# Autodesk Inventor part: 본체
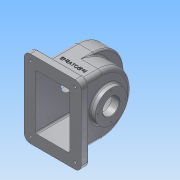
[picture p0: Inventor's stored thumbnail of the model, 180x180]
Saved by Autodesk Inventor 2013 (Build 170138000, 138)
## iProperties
Created: 2017-11
Part Number: 본체
Material: 알루미늄 6061
Document SubType Name: Modeling
Designer: Administrator
Density: 2.71 g/cm^3
Mass: 1079.31 g
Surface Area: 1186.21 cm^2
Volume: 398.271 cm^3
Author: Administrator
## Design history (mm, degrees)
sketch "스케치1"
  geometry: L1 (80, -58)-(15, -58); L2 (80, 58)-(15, 58); L3 (15, 58)-(15, -58); A1 r 58 centre (80, 0) between (80, -58) and (80, 58); 3 further points
  constraints: 6 end point, 2 horizontal alignment, 2 point on circle, 2 tangent, 1 centre point, 1 coincident, 1 horizontal, 1 parallel, 1 perpendicular
  dimensions: "d0" = 116 diameter of A1; "d7" = 15 distance from line of L3 point (0, 0); "d8" = 80 distance of point (0, 0) A1.centre
extrude "돌출1" new body sketch "스케치1" distance "d5" = 38; taper "d6" = 0 deg
sketch "스케치2"
  geometry: L1 (-58, 80)-(-58, 15) reference; L2 (-58, 15)-(58, 15) reference; L3 (58, 15)-(58, 80) reference; A1 r 58 centre (0, 80) between (58, 80) and (-58, 80) reference; A2 r 58 centre (0, 57) between (58, 57) and (-58, 57); 1 further point
  constraints: 2 point on circle, 2 point on line, 1 centre point, 1 vertical alignment
  dimensions: "d9" = 116 diameter of A2; "d11" = 57 distance of point (0, 0) A2.centre
extrude "돌출2" join sketch "스케치2" distance "d12" = 38; taper "d13" = 0 deg
sketch "스케치3"
  geometry: L1 (-93, 75)-(17, 75); L2 (17, 75)-(17, -75); L3 (17, -75)-(-93, -75); L4 (-93, -75)-(-93, 75); L5 (-93, 75)-(17, -75); L6 (17, 75)-(-93, -75); L7 (0, 58)-(0, -58) reference; L8 (0, -58)-(-76, -58) reference; L9 (-76, 58)-(-76, -58) reference; L10 (0, 58)-(-76, 58) reference; L11 (0, -58)-(0, 58) reference; L12 (0, 58)-(-38, 58) reference; L13 (-38, -58)-(-38, 58) reference; L14 (0, -58)-(-38, -58) reference; 2 further points
  constraints: 12 end point, 2 midpoint, 2 parallel, 1 horizontal, 1 perpendicular
  dimensions: "d14" = 110 distance of L2.end L3.end; "d16" = 150 distance of L1.end L2.end; "d17" = 55 horizontal distance of L13.start L2.end; "d18" = 75 distance from line of point (0, 0) L3
extrude "돌출3" join sketch "스케치3" distance "d19" = 15; taper "d20" = 0 deg
feature "쉘1" dims "d21" = 20, "d22" = 5
fillet "모깎기1" dims "d23" = 12, "d24" = 3, "d25" = 8
sketch "스케치4"
  geometry: L1 (63, 0)-(-63, 0) reference; C1 r 37.5 at (0, 65); A1 r 50 centre (0, 80) between (50, 80) and (-50, 80) reference; 1 further point
  constraints: 1 centre point, 1 vertical alignment
  dimensions: "d26" = 75 diameter of C1; "d27" = 65 distance from line of L1 C1.centre
extrude "돌출4" join sketch "스케치4" distance "d28" = 9; taper "d29" = 0 deg
sketch "스케치5"
  geometry: L1 (63, 0)-(-63, 0) reference; C1 r 31 at (0, 65); A1 r 50 centre (0, 57) between (50, 57) and (-50, 57) reference; 1 further point
  constraints: 1 centre point, 1 vertical alignment
  dimensions: "d30" = 62 diameter of C1; "d31" = 65 distance from line of L1 C1.centre
extrude "돌출5" join sketch "스케치5" distance "d32" = 10; taper "d33" = 0 deg
hole "구멍1" diameter "d37" = 32; stored, may be unused: countersink angle "d41" = 90 deg, drill point angle "d43" = 118 deg; dims "d35" = 10, "d36" = 10, "d38" = 6, "d39" = 4, "d40" = 2, "d42" = 8
sketch "스케치6" dims "d44" = 58
  geometry: L1 (0, 0)-(0, 29); C1 r 37.5 at (0, 0) reference; 1 further point
  constraints: 2 end point, 1 coincident, 1 vertical, 1 vertical alignment, 2 other
hole "구멍2" sketch "스케치6" at (0, 29) diameter "d45" = 2.459; stored, may be unused: countersink angle "d49" = 90 deg, drill point angle "d51" = 118 deg; dims "d46" = 6, "d47" = 4, "d48" = 2, "d50" = 8
sketch "스케치7" dims "d55" = 52
  geometry: L1 (0, 0)-(0, 26); C1 r 31 at (0, 0) reference; 1 further point
  constraints: 2 end point, 1 coincident, 1 vertical, 1 vertical alignment, 2 other
hole "구멍3" sketch "스케치7" at (0, 26) diameter "d56" = 2.459; stored, may be unused: countersink angle "d60" = 90 deg, drill point angle "d62" = 118 deg; dims "d57" = 6, "d58" = 4, "d59" = 2, "d61" = 8
node "작업 평면1"
sketch "스케치8"
  geometry: C1 r 6 at (-19, 0); 1 further point
  constraints: 1 centre point, 1 horizontal alignment
  dimensions: "d67" = 19 distance of C1.centre point (0, 0); "d68" = 12 diameter of C1
extrude "돌출6" join sketch "스케치8" stored distance "d69" = 10; taper "d70" = 0 deg
fillet "모깎기2" dims "d34" = 3
hole "구멍4" diameter "d73" = 4.459; stored, may be unused: countersink angle "d77" = 90 deg, drill point angle "d79" = 118 deg; dims "d71" = 10, "d72" = 10, "d74" = 6, "d75" = 4, "d76" = 2, "d78" = 8
sketch "스케치9"
  geometry: A1 r 9 centre (81, -63) between (81, -72) and (90, -63) reference; A2 r 9 centre (81, 63) between (90, 63) and (81, 72) reference; A3 r 9 centre (-5, 63) between (-5, 72) and (-14, 63) reference; A4 r 9 centre (-5, -63) between (-14, -63) and (-5, -72) reference; 1 further point
hole "구멍5" sketch "스케치9" at (-5, -63), (81, -63), (-5, 63), (81, 63) diameter "d80" = 5; stored, may be unused: countersink angle "d84" = 90 deg, drill point angle "d86" = 0 deg; dims "d81" = 6, "d82" = 12, "d83" = 5, "d85" = 8
sketch "스케치10"
  geometry: L1 (-35, 23)-(-35, -39) reference; L2 (-40, -57)-(-52, -57) reference; 2 further points
  constraints: 1 other
  dimensions: "d87" = 38 distance from line of point (3, -17) L1; "d88" = 40 distance from line of point (3, -17) L2
feature "엠보싱1" sketch "스케치10" dims "d0" = 116, "d7" = 15, "d8" = 80, "d14" = 110, "d16" = 150, "d17" = 55, "d18" = 75, "d89" = 0.5, "d90" = 0
chamfer "모따기1" distance "d91" = 1; stored, may be unused: second distance "d92" = 2, angle "d93" = 45 deg
node "솔리드1"
pattern_circular "원형 패턴1" dims angle "d53" = 360 deg
pattern_circular "원형 패턴2" dims angle "d64" = 360 deg
node "투영된 루프1"
node "투영된 루프2"
other parameters: "d66" = 144
